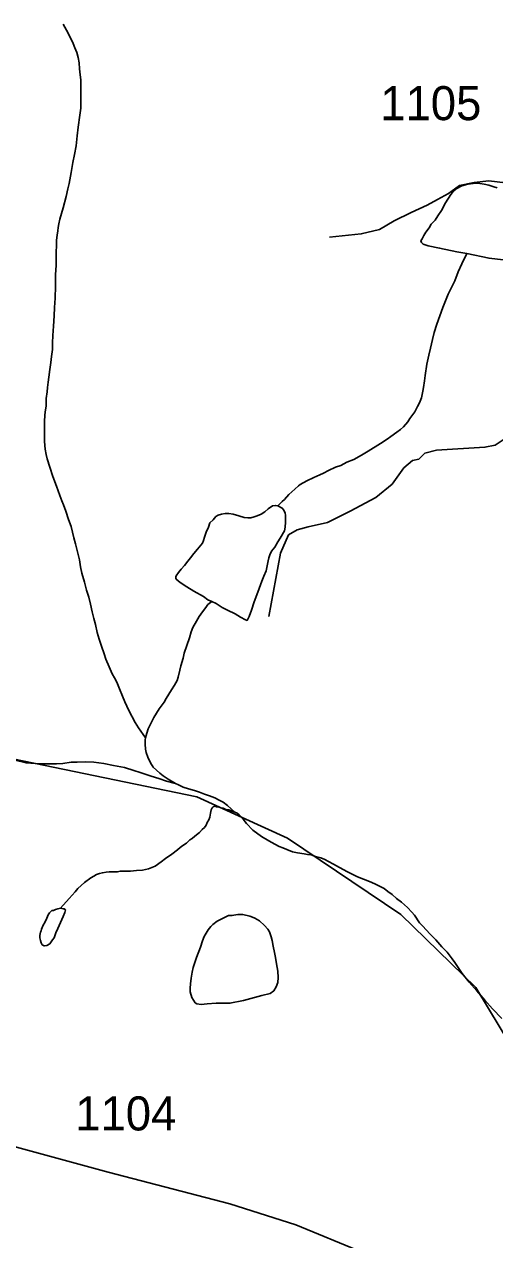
# Model space of a CAD drawing. Extents: x 2001466 to 2224147, y 644118 to 847247.
# Drawn here: x 2050483 to 2052213, y 667157 to 671619 of the extents above; entities that cross this region are included whole.
import ezdxf

# ---------------------------------------------------------------- set-up
doc = ezdxf.new("R2010")
doc.units = 0
for name, color, linetype in [('Exist Hydrographic Creek Single Shore', 7, 'Continuous'), ('Exist Hydrographic Misc Water Feature', 7, 'Continuous'), ('Exist Road Non-System Type 51', 7, 'Continuous'), ('Exist Road Secondary Type 51 Attributed', 7, 'Continuous'), ('Exist Road Secondary Type 51 Number Label', 7, 'Continuous')]:
    doc.layers.add(name, color=color, linetype=linetype)

msp = doc.modelspace()

# ---------------------------------------------------------------- linework, layer by layer
at = {"layer": 'Exist Hydrographic Creek Single Shore'}
msp.add_lwpolyline([(2053017.7, 666872.7), (2052736.4, 667325.2), (2052319.3, 667793), (2052143.4, 668082), (2051868.4, 668350), (2051451.4, 668630.9), (2051117.3, 668781.9), (2050292.4, 668952.9), (2050134.3, 669028.3), (2049975.4, 669271), (2049847.4, 669402.6)], dxfattribs=at)
at = {"layer": 'Exist Hydrographic Misc Water Feature'}
for points in [[(2050626.8, 671618.7), (2050644.9, 671586.7), (2050662.9, 671548.8), (2050669.1, 671532.8), (2050677.1, 671514.8), (2050681.2, 671496.8), (2050685.1, 671476.8), (2050687.1, 671454.8), (2050689.2, 671432.8), (2050691.2, 671414.8), (2050691.4, 671398.8), (2050691.4, 671360.8), (2050691.4, 671336.9), (2050691.4, 671310.9), (2050687.5, 671284.9), (2050681.6, 671240.9), (2050677.5, 671208.9), (2050673.8, 671172.9), (2050667.7, 671140.8), (2050661.9, 671110.8), (2050655.8, 671074.8), (2050648, 671034.8), (2050643.9, 671014.8), (2050638.1, 670986.8), (2050626, 670944.8), (2050614.1, 670902.8), (2050610.2, 670886.7), (2050608.2, 670872.7), (2050606.3, 670860.8), (2050604.3, 670844.8), (2050602.2, 670826.8), (2050600.4, 670762.8), (2050600.4, 670734.8), (2050598.5, 670698.8), (2050598.8, 670656.8), (2050596.7, 670612.8), (2050594.9, 670578.8), (2050592.8, 670548.8), (2050591, 670510.8), (2050588.9, 670476.8), (2050587.1, 670448.8), (2050587.1, 670424.8), (2050583.2, 670398.8), (2050581.1, 670376.8), (2050577.2, 670350.8), (2050573.3, 670322.8), (2050571.3, 670304.8), (2050569.2, 670284.8), (2050567.4, 670268.8), (2050563.5, 670244.8), (2050563.5, 670216.8), (2050561.4, 670202.8), (2050559.6, 670184.8), (2050557.5, 670158.8), (2050557.5, 670144.8), (2050557.7, 670122.8), (2050557.7, 670086.8), (2050559.8, 670058.8), (2050563.9, 670038.9), (2050567.8, 670022.9), (2050577.8, 669992.9), (2050587.9, 669958.9), (2050601.8, 669922.9), (2050614.1, 669889), (2050622.1, 669869), (2050628.1, 669855), (2050636.3, 669831), (2050646.1, 669801), (2050656.4, 669775.1), (2050666.2, 669733.1), (2050672.4, 669711.1), (2050686.5, 669653.1), (2050690.6, 669627.2), (2050694.5, 669603.2), (2050704.6, 669571.2), (2050712.8, 669541.2), (2050720.8, 669515.2), (2050726.7, 669489.3), (2050732.9, 669461.3), (2050738.8, 669437.3), (2050745, 669415.3), (2050750.9, 669385.3), (2050758.9, 669361.3), (2050767.1, 669335.4), (2050776.9, 669307.4), (2050783.1, 669287.4), (2050795.2, 669259.4), (2050807.1, 669233.5), (2050815.1, 669219.5), (2050823.3, 669203.5), (2050833.3, 669179.5), (2050845.2, 669151.6), (2050853.4, 669131.6), (2050867.4, 669099.6), (2050891.6, 669055.6), (2050903.5, 669035.7), (2050929.7, 668999.7)], [(2052110.2, 670777.6), (2052074.1, 670783.5), (2052010.1, 670797.4), (2051968.1, 670805.3), (2051950, 670811.3), (2051944.1, 670817.3), (2051942, 670823.3), (2051946.2, 670831.3), (2051952.1, 670843.3), (2051960.1, 670855.3), (2051972, 670871.4), (2051980, 670885.4), (2051993.9, 670899.4), (2052004, 670915.3), (2052017.9, 670935.4), (2052031.9, 670963.4), (2052051.8, 670993.5), (2052057.7, 671001.5), (2052073.7, 671015.5), (2052091.7, 671025.5), (2052105.7, 671029.6), (2052115.7, 671031.6), (2052141.8, 671035.6), (2052157.8, 671033.7), (2052173.8, 671031.7), (2052191.6, 671027.7), (2052209.6, 671021.7), (2052221.7, 671017.8)], [(2052110.2, 670777.6), (2052092.1, 670739.6), (2052078.4, 670709.5), (2052066.3, 670677.5), (2052056.3, 670657.5), (2052042.5, 670627.5), (2052022.6, 670579.5), (2052000.7, 670517.5), (2051990.6, 670487.4), (2051984.7, 670461.4), (2051976.9, 670429.4), (2051970.8, 670403.4), (2051963, 670371.4), (2051957, 670329.4), (2051955, 670309.4), (2051951.1, 670285.4), (2051949, 670271.4), (2051943.3, 670247.4), (2051937.1, 670229.4), (2051929.1, 670215.3), (2051919.1, 670195.4), (2051901.2, 670171.4), (2051893.2, 670159.3), (2051877.3, 670141.3), (2051867.2, 670131.3), (2051853.5, 670121.2), (2051831.5, 670105.2), (2051817.4, 670095.1), (2051793.4, 670079.1), (2051747.5, 670051.1), (2051723.5, 670037), (2051695.6, 670021), (2051669.7, 670010.9), (2051647.6, 669998.9), (2051627.7, 669992.8), (2051601.7, 669980.8), (2051583.6, 669970.8), (2051569.7, 669964.7), (2051547.7, 669954.7), (2051521.9, 669942.6), (2051497.7, 669928.6), (2051491.8, 669924.6), (2051477.8, 669912.6), (2051455.9, 669892.5), (2051439.9, 669874.5), (2051431.9, 669866.5), (2051415.9, 669850.5)], [(2052244.1, 670753.9), (2052192.2, 670759.7), (2052110.2, 670777.6)], [(2051415.9, 669850.5), (2051407.9, 669852.5), (2051396, 669850.5), (2051380, 669840.4), (2051368.1, 669828.4), (2051354, 669820.4), (2051340, 669814.3), (2051328.1, 669810.3), (2051316, 669806.3), (2051306, 669806.3), (2051292, 669808.3), (2051272.1, 669814.2), (2051252, 669820.2), (2051236.1, 669822.2), (2051222.1, 669822.2), (2051208, 669820.1), (2051196.1, 669816.1), (2051188.1, 669812.1), (2051178, 669800), (2051166.1, 669788), (2051160.2, 669772), (2051152.2, 669754), (2051146.2, 669736), (2051142.3, 669724), (2051138.2, 669714), (2051132.3, 669705.9), (2051120.2, 669692), (2051106.3, 669676), (2051094.4, 669659.9), (2051084.3, 669647.9), (2051072.4, 669631.9), (2051060.3, 669617.8), (2051050.5, 669605.8), (2051042.5, 669593.8), (2051040.6, 669589.8), (2051040.6, 669585.8), (2051042.5, 669581.8), (2051056.6, 669569.9), (2051080.6, 669553.9), (2051106.5, 669538), (2051142.8, 669518), (2051158.8, 669506.1), (2051172.7, 669500.1)], [(2051172.7, 669500.1), (2051188.7, 669492.1), (2051210.6, 669478.1), (2051230.7, 669468.2), (2051258.6, 669454.2), (2051278.7, 669442.3), (2051296.8, 669432.3), (2051302.7, 669430.3), (2051310.7, 669444.4), (2051318.7, 669468.4), (2051328.7, 669498.4), (2051342.5, 669534.4), (2051356.4, 669574.4), (2051364.4, 669592.5), (2051372.4, 669612.4), (2051376.5, 669630.4), (2051380.2, 669648.5), (2051382.3, 669660.5), (2051386.4, 669670.5), (2051392.3, 669684.5), (2051404.2, 669698.5), (2051416.1, 669718.5), (2051424.1, 669732.5), (2051440.1, 669758.5), (2051442.1, 669772.5), (2051444, 669790.5), (2051444, 669806.5), (2051444, 669816.5), (2051442.1, 669824.5), (2051438, 669834.5), (2051431.9, 669842.5), (2051415.9, 669850.5)], [(2051172.7, 669500.1), (2051158.8, 669488.1), (2051150.8, 669478.1), (2051138.7, 669462), (2051126.8, 669444), (2051116.7, 669428), (2051102.8, 669404), (2051096.8, 669388), (2051090.9, 669366), (2051080.8, 669337.9), (2051071, 669309.9), (2051067.1, 669291.9), (2051059.1, 669264), (2051055.2, 669247.9), (2051049.3, 669221.9), (2051045.2, 669209.9), (2051035.3, 669191.9), (2051025.3, 669175.9), (2051015.2, 669159.9), (2051005.4, 669143.8), (2050997.4, 669129.8), (2050979.3, 669105.8), (2050969.5, 669089.8), (2050959.4, 669073.8), (2050947.5, 669049.8), (2050939.5, 669031.7), (2050933.6, 669015.7), (2050929.7, 668999.7)], [(2050929.7, 668999.7), (2050927.7, 668991.7), (2050927.7, 668975.7), (2050929.7, 668957.8), (2050931.6, 668945.8), (2050937.7, 668927.8), (2050947.8, 668907.8), (2050957.8, 668891.8), (2050969.7, 668879.8), (2050981.8, 668869.8), (2050993.9, 668859.9), (2051011.9, 668847.9), (2051039.8, 668832)], [(2050449.9, 668916.9), (2050489.9, 668907), (2050523.9, 668905), (2050552, 668903.1), (2050581.9, 668903.1), (2050601.8, 668903.1), (2050625.8, 668905.2), (2050655.8, 668909.3), (2050677.7, 668909.3), (2050709.7, 668911.3), (2050739.8, 668909.4), (2050775.7, 668905.4), (2050811.8, 668897.5), (2050851.8, 668889.6), (2050885.8, 668879.7), (2050909.8, 668871.7), (2050949.8, 668857.8), (2050977.9, 668849.8), (2051006, 668839.9), (2051039.8, 668832)], [(2051039.8, 668832), (2051049.9, 668826), (2051067.9, 668818), (2051087.8, 668812.1), (2051109.9, 668806.1), (2051128, 668800.1), (2051145.8, 668792.1), (2051163.9, 668786.2), (2051184, 668778.3), (2051200, 668770.2), (2051214.1, 668762.4), (2051230.1, 668750.4), (2051244.1, 668738.4), (2051257, 668726), (2051266, 668722.4)], [(2050836.4, 668509.6), (2050874.5, 668509.7), (2050896.5, 668511.8), (2050918.4, 668513.8), (2050940.6, 668517.8), (2050964.4, 668527.9), (2050986.3, 668544), (2051002.3, 668556), (2051026.3, 668572), (2051046.2, 668588), (2051056.2, 668596), (2051066.3, 668604.1), (2051080.2, 668612.1), (2051092.3, 668624.1), (2051100.3, 668630.1), (2051110.4, 668638.1), (2051128.2, 668652.1), (2051138, 668662.2), (2051146, 668670.2), (2051152.2, 668678.2), (2051156.1, 668688.2), (2051162.2, 668698.2), (2051166.1, 668708.2), (2051168, 668722.2), (2051170, 668734.2), (2051173.9, 668742.2), (2051178, 668746.3), (2051184, 668748.3), (2051189.9, 668746.3), (2051200, 668744.3), (2051205.9, 668742.3), (2051214.1, 668740.3), (2051224, 668736.3), (2051236.1, 668734.3), (2051257, 668726), (2051266, 668722.4)], [(2051266, 668722.4), (2051274, 668716.4), (2051287.9, 668700.5), (2051300.2, 668684.5), (2051324.2, 668660.5), (2051356.2, 668636.6), (2051382.1, 668620.7), (2051404.2, 668608.7), (2051420.2, 668600.7), (2051434.3, 668594.8), (2051448.3, 668588.8), (2051470.2, 668580.8), (2051488.3, 668576.8), (2051512.3, 668572.9), (2051524.4, 668570.9), (2051538.3, 668569), (2051554.3, 668563), (2051574.2, 668559), (2051588.3, 668553), (2051602.3, 668545.1), (2051620.3, 668535.1), (2051642.5, 668523.2), (2051672.4, 668507.2), (2051708.3, 668489.3)], [(2050616.6, 668373.3), (2050648.8, 668409.3), (2050670.7, 668433.4), (2050680.6, 668445.4), (2050692.7, 668457.4), (2050704.6, 668467.4), (2050728.6, 668485.4), (2050738.6, 668491.4), (2050748.4, 668497.5), (2050760.5, 668501.5), (2050770.6, 668503.5), (2050784.5, 668505.6), (2050796.4, 668507.6), (2050826.6, 668507.6), (2050836.4, 668509.6)], [(2051708.3, 668489.3), (2051752.4, 668471.3), (2051772.5, 668463.4), (2051806.3, 668445.5), (2051820.5, 668435.4), (2051836.4, 668423.6), (2051852.4, 668409.6), (2051870.5, 668395.6), (2051892.4, 668375.7), (2051908.6, 668359.7), (2051918.7, 668347.7), (2051936.7, 668319.7), (2051948.6, 668307.8), (2051974.7, 668279.8), (2051996.8, 668257.9), (2052018.7, 668231.9), (2052038.8, 668212), (2052056.9, 668188), (2052066.9, 668174), (2052093, 668134), (2052119, 668102.1), (2052146.9, 668070.1), (2052177, 668036.2), (2052205.1, 668004.3), (2052239.2, 667968.3)], [(2050616.6, 668373.3), (2050606.8, 668371.3), (2050598.8, 668369.3), (2050590.8, 668365.2), (2050584.8, 668365.2), (2050576.8, 668357.2), (2050570.9, 668349.2), (2050567, 668337.2), (2050559, 668321.2), (2050552.8, 668311.1), (2050546.9, 668297.1), (2050545, 668291.1), (2050543, 668285.1), (2050540.9, 668273.1), (2050540.9, 668265.1), (2050543, 668255.2), (2050545, 668247.1), (2050548.9, 668239.2), (2050556.9, 668235.2), (2050567, 668237.2), (2050577, 668243.2), (2050587.1, 668257.3), (2050593, 668265.3), (2050599, 668283.2), (2050607, 668299.2), (2050616.8, 668321.2), (2050626.8, 668343.3), (2050632.8, 668357.3), (2050634.8, 668367.3), (2050630.7, 668371.3), (2050626.8, 668371.3), (2050616.6, 668373.3)], [(2051322.8, 668340.6), (2051312.7, 668344.6), (2051286.7, 668350.5), (2051268.7, 668350.5), (2051246.7, 668346.5), (2051234.8, 668346.4), (2051212.7, 668336.4), (2051192.8, 668326.3), (2051176.8, 668314.3), (2051168.8, 668306.3), (2051159, 668294.3), (2051144.8, 668270.3), (2051138.9, 668254.3), (2051131.1, 668230.3), (2051116.9, 668192.2), (2051111, 668174.2), (2051105, 668156.2), (2051101.1, 668138.2), (2051097, 668116.2), (2051095.2, 668096.2), (2051093.3, 668080.2), (2051093.3, 668066.2), (2051099.3, 668046.2), (2051105.4, 668036.3), (2051111.4, 668026.3), (2051117.3, 668022.3), (2051133.3, 668020.3), (2051155.5, 668022.3), (2051189.3, 668024.4), (2051239.3, 668024.5), (2051289.2, 668034.6), (2051357.2, 668052.7), (2051387.2, 668060.8), (2051401.3, 668070.8), (2051409.1, 668084.8), (2051415.1, 668100.7), (2051417.1, 668118.8), (2051415.1, 668142.8), (2051411, 668168.8), (2051407.1, 668192.8), (2051403, 668210.8), (2051398.9, 668234.8), (2051395, 668254.7), (2051390.9, 668268.7), (2051384.7, 668286.7), (2051378.8, 668296.7), (2051366.7, 668310.7), (2051348.8, 668326.7), (2051330.8, 668336.6), (2051322.8, 668340.6)]]:
    msp.add_lwpolyline(points, dxfattribs=at)
at = {"layer": 'Exist Road Non-System Type 51'}
for points in [[(2052335.1, 671027.4), (2052192, 671043.6), (2052138, 671038.2), (2052084, 671027.4), (2052043.5, 670997.6), (2052003, 670976), (2051965.2, 670954.4), (2051905.8, 670927.4), (2051843.7, 670897.7), (2051789.7, 670865.3), (2051722.2, 670849.1), (2051605.3, 670836.8)], [(2051934.2, 670022.5), (2051955.8, 670044.1), (2051999, 670054.9), (2052177.2, 670065.7), (2052215, 670073.8), (2052247.4, 670095.4), (2052260.9, 670122.4), (2052263.6, 670192.7), (2052269, 670235.9), (2052312.2, 670271), (2052414.8, 670327.5)], [(2051934.2, 670022.5), (2051911.2, 670017.1), (2051878.8, 669990.1), (2051835.6, 669930.7), (2051776.2, 669882), (2051681.7, 669830.7), (2051598, 669790.2), (2051527.8, 669774), (2051487.3, 669763.2), (2051454.9, 669744.3), (2051425.2, 669676.7), (2051382, 669444.4)]]:
    msp.add_lwpolyline(points, dxfattribs=at)
at = {"layer": 'Exist Road Secondary Type 51 Attributed'}
msp.add_lwpolyline([(2052557.1, 666646.2), (2052386.3, 666764), (2052162.5, 666885.4), (2051899.2, 667023.8), (2051726.1, 667110.4), (2051482.2, 667211.8), (2051238.9, 667288.9), (2050792.4, 667405.1), (2050170.2, 667573.1), (2049959.6, 667625.9), (2049883.6, 667635.4), (2049783.3, 667640.7), (2049542.6, 667618.5), (2049242.3, 667606.9)], dxfattribs=at)

# ---------------------------------------------------------------- texts
at = {"layer": 'Exist Road Secondary Type 51 Number Label'}
for s, p in [('1105', (2051792.1, 671266.7)), ('1104', (2050670.7, 667557.7))]:
    msp.add_text(s, height=125, dxfattribs=at).set_placement(p)

doc.saveas('drawing.dxf')
